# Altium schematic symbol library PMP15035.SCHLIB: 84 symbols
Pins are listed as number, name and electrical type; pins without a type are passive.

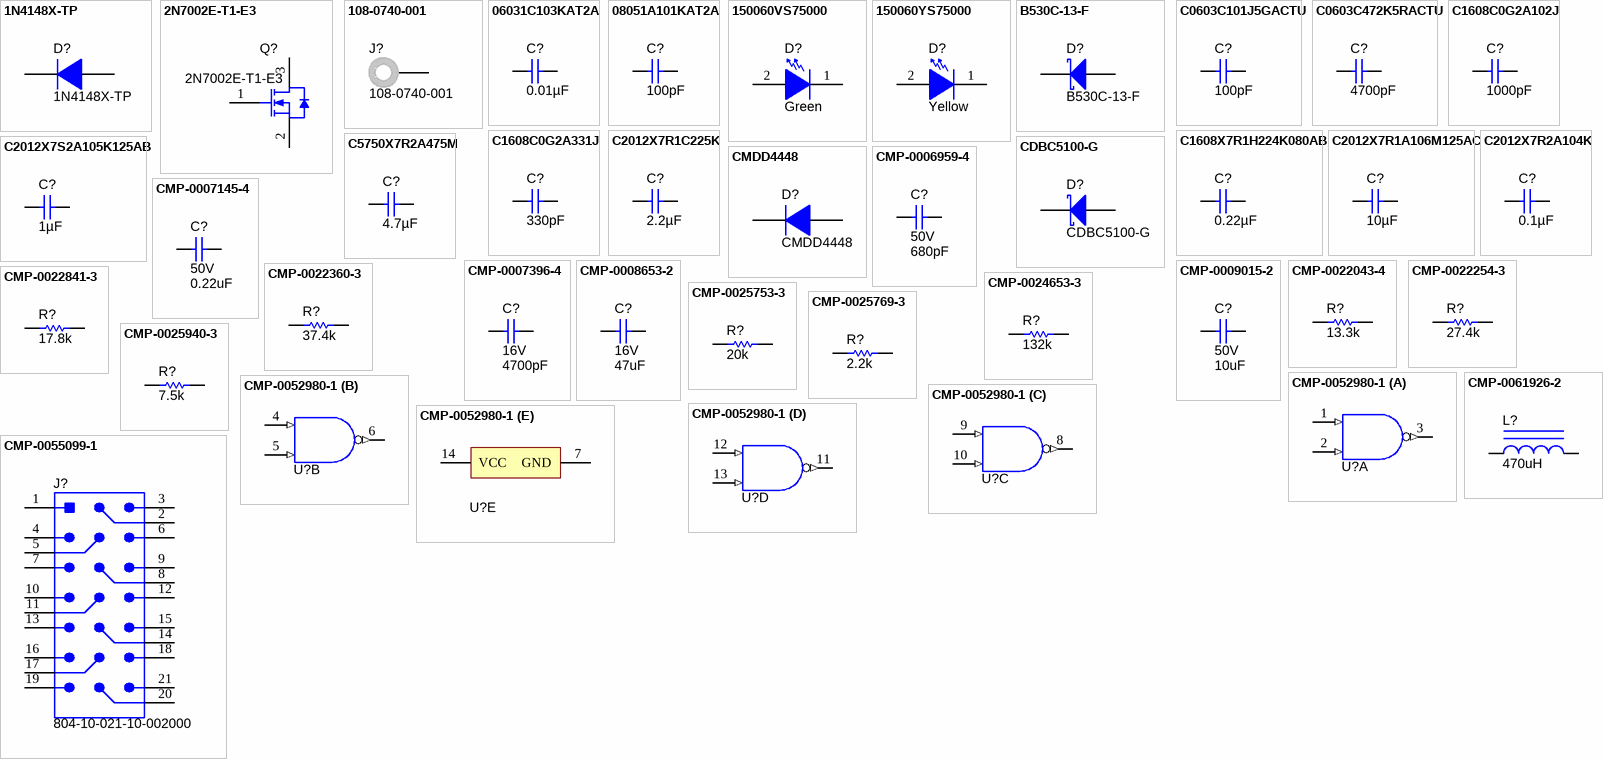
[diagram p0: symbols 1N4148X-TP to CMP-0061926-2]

## 1N4148X-TP
designator D?
Diode, Switching, 75 V, 0.3 A, SOD-523; Manufacturer: Micro Commercial Components; U/M: EA; Vf_V: 1.25; Value: 75V; Value1: 0.3A; Value2: 1.25V; Io_A: 0.3; Vr_V: 75; TJmax_C: 150; RJC_CperW: 625
signal-integrity model Diode
footprint SOD-523
pins: 1 K, 2 A

## 2N7002E-T1-E3
designator Q?
MOSFET, N-CH, 60 V, 0.24 A, SOT-23; Manufacturer: Vishay-Siliconix; Alternate Manufacturer: None; U/M: EA; ChType: N; Value: 60V; VdsMax_V: 60; Value1: 1.8 ohm; Rdson45_ohm: 1.8; Value2: 0.4 nC; QgTyp_nC: 0.4; Vgs_V: 20; IdsMax_A: 0.24
footprint SOT-23
footprint SOT-23M
footprint SOT-23L
simulation model 2N7002E
pins: 1 G, 2 S, 3 D

## 108-0740-001
designator J?
Standard Banana Jack, Uninsulated, 15A; Manufacturer: Emerson Network Power; SymbolCreator: a0412235; CompType: Connector; U/M: EA
footprint Johnson_108-0740-001
pins: 1

## 06031C103KAT2A
designator C?  ValueDisplayed: 0.01µF  (hidden comment: 06031C103KAT2A)
CAP, CERM, 0.01 µF, 100 V, +/- 10%, X7R, 0603; Manufacturer: AVX; Polarized: N; CompType: Capacitor; Value: 0.01uF; U/M: EA; Cap_F: 0.00000001; Tolerance_%: 10; ESR_ohm: 0.098; Value1: 0.098 ohm; VDC_V: 100; Value2: 100V; TaMin_C: -55; TaMax_C: 125; Cap_Case: 0603
signal-integrity model Cap
simulation model Cap
footprint 0603
footprint 0603M
footprint 0603L
footprint 0603_HV
footprint 0603S
pins: 1, 2

## 08051A101KAT2A
designator C?  ValueDisplayed: 100pF  (hidden comment: 08051A101KAT2A)
CAP, CERM, 100 pF, 100 V, +/- 10%, C0G/NP0, 0805; Manufacturer: AVX; Polarized: N; CompType: Capacitor; Value: 100pF; U/M: EA; Cap_F: 0.0000000001; Tolerance_%: 10; ESR_ohm: 0.356; Value1: 0.356 ohm; VDC_V: 100; Value2: 100V; TaMin_C: -55; TaMax_C: 125; Cap_Case: 0805
signal-integrity model Cap
simulation model Cap
footprint 0805_HV
footprint 0805
footprint 0805M
footprint 0805L
pins: 1, 2

## 150060VS75000
designator D?  value Green  (hidden comment: 150060VS75000)
LED, Green, SMD; Manufacturer: Wurth Elektronik; Type: AlInGaP; Vf_V: 2; Value2: 2V; Io_A: 0.02; Value1: W; U/M: EA
signal-integrity model Diode
footprint WL-SMCW_GREEN
pins: 1 K, 2 A

## 150060YS75000
designator D?  value Yellow  (hidden comment: 150060YS75000)
LED, Yellow, SMD; Manufacturer: Wurth Elektronik; Type: AlInGaP; Vf_V: 2; Value2: 2V; Io_A: 0.02; Value1: W; U/M: EA
signal-integrity model Diode
footprint WL-SMCW_YELLOW
pins: 1 K, 2 A

## B530C-13-F
designator D?
Diode, Schottky, 30 V, 5 A, SMC; Manufacturer: Diodes Inc.; U/M: EA; Vf_V: 0.55; Value: 30V; Value1: 5A; Value2: 0.55V; Io_A: 5; Vr_V: 30; TJmax_C: 125; RJC_CperW: 10
signal-integrity model Diode
simulation model DI_B530C
footprint SMC
pins: 1 K, 2 A

## C0603C101J5GACTU
designator C?  ValueDisplayed: 100pF  (hidden comment: C0603C101J5GACTU)
CAP, CERM, 100 pF, 50 V, +/- 5%, C0G/NP0, 0603; Manufacturer: Kemet; Polarized: N; CompType: Capacitor; Value: 100pF; U/M: EA; Cap_F: 0.0000000001; Tolerance_%: 5; Value1: Unknown; VDC_V: 50; Value2: 50V; TaMin_C: -55; TaMax_C: 125; Cap_Case: 0603; AEC Category: Q200
signal-integrity model Cap
simulation model Cap
footprint 0603
footprint 0603M
footprint 0603L
footprint 0603_HV
footprint 0603S
pins: 1, 2

## C0603C472K5RACTU
designator C?  ValueDisplayed: 4700pF  (hidden comment: C0603C472K5RACTU)
CAP, CERM, 4700 pF, 50 V, +/- 10%, X7R, 0603; Manufacturer: Kemet; Polarized: N; CompType: Capacitor; Value: 4700pF; U/M: EA; Cap_F: 0.0000000047; Tolerance_%: 10; Value1: Unknown; VDC_V: 50; Value2: 50V; TaMin_C: -55; TaMax_C: 125; Cap_Case: 0603; AEC Category: Q200
signal-integrity model Cap
simulation model Cap
footprint 0603
footprint 0603M
footprint 0603L
footprint 0603_HV
footprint 0603S
pins: 1, 2

## C1608C0G2A102J
designator C?  ValueDisplayed: 1000pF  (hidden comment: C1608C0G2A102J)
CAP, CERM, 1000 pF, 100 V, +/- 5%, C0G/NP0, 0603; Manufacturer: TDK; Polarized: N; CompType: Capacitor; Value: 1000pF; U/M: EA; Cap_F: 0.000000001; Tolerance_%: 5; ESR_ohm: 0.0589; Value1: 0.0589 ohm; VDC_V: 100; Value2: 100V; TaMin_C: -55; TaMax_C: 125; Cap_Case: 0603
signal-integrity model Cap
simulation model Cap
footprint 0603
footprint 0603M
footprint 0603L
footprint 0603_HV
footprint 0603S
pins: 1, 2

## C1608C0G2A331J
designator C?  ValueDisplayed: 330pF  (hidden comment: C1608C0G2A331J)
CAP, CERM, 330 pF, 100 V, +/- 5%, C0G/NP0, 0603; Manufacturer: TDK; Polarized: N; CompType: Capacitor; Value: 330pF; U/M: EA; Cap_F: 0.00000000033; Tolerance_%: 5; ESR_ohm: 0.1269; Value1: 0.1269 ohm; VDC_V: 100; Value2: 100V; TaMin_C: -55; TaMax_C: 125; Cap_Case: 0603
signal-integrity model Cap
simulation model Cap
footprint 0603
footprint 0603M
footprint 0603L
footprint 0603_HV
footprint 0603S
pins: 1, 2

## C1608X7R1H224K080AB
designator C?  ValueDisplayed: 0.22µF  (hidden comment: C1608X7R1H224K080AB)
CAP, CERM, 0.22 µF, 50 V, +/- 10%, X7R, 0603; Manufacturer: TDK; Polarized: N; CompType: Capacitor; Value: 0.22uF; U/M: EA; Cap_F: 0.00000022; Tolerance_%: 10; Value1: Unknown; VDC_V: 50; Value2: 50V; TaMin_C: -55; TaMax_C: 125; Cap_Case: 0603
signal-integrity model Cap
simulation model Cap
footprint 0603
footprint 0603M
footprint 0603L
footprint 0603_HV
footprint 0603S
pins: 1, 2

## C2012X7R1A106M125AC
designator C?  ValueDisplayed: 10µF  (hidden comment: C2012X7R1A106M125AC)
CAP, CERM, 10 µF, 10 V, +/- 20%, X7R, 0805; Manufacturer: TDK; Polarized: N; CompType: Capacitor; Value: 10uF; U/M: EA; Cap_F: 0.00001; Tolerance_%: 20; Value1: Unknown; VDC_V: 10; Value2: 10V; TaMin_C: -55; TaMax_C: 125; Cap_Case: 0805
signal-integrity model Cap
simulation model Cap
footprint 0805_145
footprint 0805_145M
footprint 0805_145L
footprint 0805_145HV
pins: 1, 2

## C2012X7R1C225K
designator C?  ValueDisplayed: 2.2µF  (hidden comment: C2012X7R1C225K)
CAP, CERM, 2.2 µF, 16 V, +/- 10%, X7R, 0805; Manufacturer: TDK; CompType: Capacitor; Value: 2.2uF; U/M: EA; Tolerance_%: 10; VDC_V: 16; Polarized: N; Cap_F: 0.0000022; ESR_ohm: 0.0049; Value1: 0.0049 ohm; Value2: 16V; TaMin_C: -55; TaMax_C: 125; Cap_Case: 0805
signal-integrity model Cap
simulation model Cap
footprint 0805_HV
footprint 0805
footprint 0805M
footprint 0805L
pins: 1, 2

## C2012X7R2A104K
designator C?  ValueDisplayed: 0.1µF  (hidden comment: C2012X7R2A104K)
CAP, CERM, 0.1 µF, 100 V, +/- 10%, X7R, 0805; Manufacturer: TDK; Polarized: N; CompType: Capacitor; Value: 0.1uF; U/M: EA; Cap_F: 0.0000001; Tolerance_%: 10; ESR_ohm: 0.0158; Value1: 0.0158 ohm; VDC_V: 100; Value2: 100V; TaMin_C: -55; TaMax_C: 125; Cap_Case: 0805
signal-integrity model Cap
simulation model Cap
footprint 0805_HV
footprint 0805
footprint 0805M
footprint 0805L
pins: 1, 2

## C2012X7S2A105K125AB
designator C?  ValueDisplayed: 1µF  (hidden comment: C2012X7S2A105K125AB)
CAP, CERM, 1 µF, 100 V, +/- 10%, X7S, 0805; Manufacturer: TDK; Polarized: N; CompType: Capacitor; Value: 1uF; U/M: EA; Cap_F: 0.000001; Tolerance_%: 10; Value1: Unknown; VDC_V: 100; Value2: 100V; TaMin_C: -55; TaMax_C: 125; Cap_Case: 0805; AEC Category: Q200
signal-integrity model Cap
simulation model Cap
footprint 0805_HV
footprint 0805_HV1
footprint 0805
footprint 0805M
footprint 0805L
pins: 1, 2

## C5750X7R2A475M
designator C?  ValueDisplayed: 4.7µF  (hidden comment: C5750X7R2A475M)
CAP, CERM, 4.7 µF, 100 V, +/- 20%, X7R, 2220; Manufacturer: TDK; Polarized: N; CompType: Capacitor; Value: 4.7uF; U/M: EA; Cap_F: 0.0000047; Tolerance_%: 20; ESR_ohm: 0.0015; Value1: 0.0015 ohm; VDC_V: 100; Value2: 100V; IRMS_A: 5.5; TaMin_C: -55; TaMax_C: 125; Cap_Case: 2220
signal-integrity model Cap
simulation model Cap
footprint 2220
footprint 2220_M
footprint 2220_L
pins: 1, 2

## CDBC5100-G
designator D?
Diode, Schottky, 100 V, 5 A, SMC; Manufacturer: Comchip Technology; U/M: EA; Vf_V: 0.85; Value: 100V; Value1: 5A; Value2: 0.85V; Io_A: 5; Vr_V: 100; TJmax_C: 125
signal-integrity model Diode
footprint SMC
pins: 1 K, 2 A

## CMDD4448
designator D?
Diode, Ultrafast, 75 V, 0.25 A, SOD-323; Manufacturer: Central Semiconductor; U/M: EA; Vf_V: 1.2; Value: 75V; Value1: 0.25A; Value2: 1.2V; Io_A: 0.25; Vr_V: 75; TJmax_C: 175
signal-integrity model Diode
simulation model CMDD4448
footprint sod-323
pins: 1 K, 2 A

## CMP-0006959-4
designator C?, comment VDC_V: 50V  ValueDisplayed: 680pF  (hidden comment: C0603C681J5GACTU)
CAP, CERM, 680 pF, 50 V, +/- 5%, C0G/NP0, 0603; Manufacturer: Kemet; TaMin_C: -55°C; Polarized: N; SizeAreaWB_mm2: 4.68; Value1: Unknown; U/M: EA; Value: 680pF; TaMax_C: 125°C; SizeZ_mm: 1; SizeX_mm: 1.6; SizeY_mm: 0.8; Cap_Case: 0603; SizeArea_mm2: 1.28; CompType: Capacitor; AEC Category: Q200
footprint 0603 (0603 from SM-752 data)
footprint 0603_HV (Ernesto recommended land pattern.  26 mil between pads.)
footprint 0603L (0603 from SM-752 data)
footprint 0603S
footprint 0603M (0603 from SM-752 data)
pins: 1, 2

## CMP-0007145-4
designator C?, comment VDC_V: 50V  ValueDisplayed: 0.22uF  (hidden comment: GCM188R71H224KA64D)
CAP, CERM, 0.22 uF, 50 V, +/- 10%, X7R, AEC-Q200 Grade 1, 0603; Manufacturer: MuRata; TaMin_C: -55°C; Polarized: N; SizeAreaWB_mm2: 4.68; Value1: Unknown; U/M: EA; Value: 0.22uF; TaMax_C: 125°C; SizeZ_mm: 1; SizeX_mm: 1.6; SizeY_mm: 0.8; Cap_Case: 0603; SizeArea_mm2: 1.28; CompType: Capacitor; AEC Qualified: Y; Cap_F: 220nF; AEC Category: Q200
footprint 0603 (0603 from SM-752 data)
footprint 0603_HV (Ernesto recommended land pattern.  26 mil between pads.)
footprint 0603L (0603 from SM-752 data)
footprint 0603S
footprint 0603M (0603 from SM-752 data)
pins: 1, 2

## CMP-0007396-4
designator C?, comment VDC_V: 16V  ValueDisplayed: 4700pF  (hidden comment: GRM188R71C472KA01D)
CAP, CERM, 4700 pF, 16 V, +/- 10%, X7R, 0603; Manufacturer: MuRata; TaMin_C: -55°C; Polarized: N; SizeAreaWB_mm2: 4.68; Value1: Unknown; U/M: EA; Value: 4700pF; TaMax_C: 125°C; SizeZ_mm: 1; SizeX_mm: 1.6; SizeY_mm: 0.8; Cap_Case: 0603; SizeArea_mm2: 1.28; Cap_F: 4.7nF; AEC Category: Q200; CompType: Capacitor
footprint 0603 (0603 from SM-752 data)
footprint 0603_HV (Ernesto recommended land pattern.  26 mil between pads.)
footprint 0603L (0603 from SM-752 data)
footprint 0603S
footprint 0603M (0603 from SM-752 data)
pins: 1, 2

## CMP-0008653-2
designator C?, comment VDC_V: 16V  ValueDisplayed: 47uF  (hidden comment: C3216X5R1C476M160AB)
CAP, CERM, 47 uF, 16 V, +/- 15%, X5R, 1206; Manufacturer: TDK; TaMin_C: -55°C; Polarized: N; SizeAreaWB_mm2: 10.92; Value1: Unknown; U/M: EA; Value: 47uF; TaMax_C: 85°C; SizeZ_mm: 1.35; SizeX_mm: 3.2; SizeY_mm: 1.6; Cap_Case: 1206; SizeArea_mm2: 5.12; CompType: Capacitor; Cap_F: 47µF; AEC Category: Q200
footprint 1206 (1206 from SM-752 data)
footprint 1206L (1206 from SM-752 data)
footprint 1206M (1206 from SM-752 data)
pins: 1, 2

## CMP-0009015-2
designator C?, comment VDC_V: 50V  ValueDisplayed: 10uF  (hidden comment: GRT31CR61H106KE01L)
CAP, CERM, 10 uF, 50 V, +/- 10%, X5R, AEC-Q200 Grade 1, 1206; Manufacturer: MuRata; TaMin_C: -55°C; Polarized: N; SizeAreaWB_mm2: 10.92; Value1: Unknown; U/M: EA; Value: 10uF; TaMax_C: 85°C; SizeZ_mm: 1.8; SizeX_mm: 3.2; SizeY_mm: 1.6; Cap_Case: 1206; SizeArea_mm2: 5.12; CompType: Capacitor; AEC Qualified: Y; Cap_F: 10µF; AEC Grade: 1; AEC Category: Q200
footprint 1206_180
footprint 1206_180L (1206_180)
footprint 1206_180M (1206_180)
pins: 1, 2

## CMP-0022043-4
designator R?, comment ValueDisplayed: 13.3k  (hidden comment: CRCW060313K3FKEA)
RES, 13.3 k, 1%, 0.1 W, AEC-Q200 Grade 0, 0603; Manufacturer: Vishay-Dale; Power_W: 100mW; TempCo: 100 ppm/C; Value_Code: 13k3; Value: 13.3k; EIA_Code: E96; SizeX_mm: 1.6; SizeY_mm: 0.8; SizeZ_mm: 1; Value2: 0.1W; SizeArea_mm2: 1.28; CompType: Resistor; AEC Qualified: Y; VDC_V: 75V; AEC Category: Q200; AEC Grade: 0
footprint 0603 (0603 from SM-752 data)
footprint 0603_HV (Ernesto recommended land pattern.  26 mil between pads.)
footprint 0603L (0603 from SM-752 data)
footprint 0603S
footprint 0603M (0603 from SM-752 data)
pins: 1, 2

## CMP-0022254-3
designator R?, comment ValueDisplayed: 27.4k  (hidden comment: CRCW060327K4FKEA)
RES, 27.4 k, 1%, 0.1 W, 0603; Manufacturer: Vishay-Dale; Power_W: 100mW; TempCo: 100 ppm/C; Value_Code: 27k4; U/M: EA; Value: 27.4k; EIA_Code: E96; SizeX_mm: 1.6; SizeY_mm: 0.8; SizeZ_mm: 1; Value2: 0.1W; SizeArea_mm2: 1.28; CompType: Resistor; VDC_V: 75V; AEC Category: Q200
footprint 0603 (0603 from SM-752 data)
footprint 0603_HV (Ernesto recommended land pattern.  26 mil between pads.)
footprint 0603L (0603 from SM-752 data)
footprint 0603S
footprint 0603M (0603 from SM-752 data)
pins: 1, 2

## CMP-0022360-3
designator R?, comment ValueDisplayed: 37.4k  (hidden comment: CRCW060337K4FKEA)
RES, 37.4 k, 1%, 0.1 W, 0603; Manufacturer: Vishay-Dale; Power_W: 100mW; TempCo: 100 ppm/C; Value_Code: 37k4; U/M: EA; Value: 37.4k; EIA_Code: E96; SizeX_mm: 1.6; SizeY_mm: 0.8; SizeZ_mm: 1; Value2: 0.1W; SizeArea_mm2: 1.28; CompType: Resistor; VDC_V: 75V; AEC Category: Q200
footprint 0603 (0603 from SM-752 data)
footprint 0603_HV (Ernesto recommended land pattern.  26 mil between pads.)
footprint 0603L (0603 from SM-752 data)
footprint 0603S
footprint 0603M (0603 from SM-752 data)
pins: 1, 2

## CMP-0022841-3
designator R?, comment ValueDisplayed: 17.8k  (hidden comment: RC0603FR-0717K8L)
RES, 17.8 k, 1%, 0.1 W, 0603; Manufacturer: Yageo America; Power_W: 100mW; TempCo: 200 ppm/C; Value_Code: 17k8; U/M: EA; Value: 17.8k; EIA_Code: E96; SizeX_mm: 1.6; SizeY_mm: 0.8; SizeZ_mm: 1; Value2: 0.1W; SizeArea_mm2: 1.28; CompType: Resistor; VDC_V: 150V; AEC Category: Q200
footprint 0603 (0603 from SM-752 data)
footprint 0603_HV (Ernesto recommended land pattern.  26 mil between pads.)
footprint 0603L (0603 from SM-752 data)
footprint 0603S
footprint 0603M (0603 from SM-752 data)
pins: 1, 2

## CMP-0024653-3
designator R?, comment ValueDisplayed: 132k  (hidden comment: RT0603DRE07132KL)
RES, 132 k, 0.5%, 0.1 W, 0603; Manufacturer: Yageo America; Power_W: 100mW; TempCo: 50 ppm/C; U/M: EA; Value: 132k; EIA_Code: E192; SizeX_mm: 1.6; SizeY_mm: 0.8; SizeZ_mm: 1; Value2: 0.1W; SizeArea_mm2: 1.28; CompType: Resistor; VDC_V: 75V; AEC Category: Q200
footprint 0603 (0603 from SM-752 data)
footprint 0603_HV (Ernesto recommended land pattern.  26 mil between pads.)
footprint 0603L (0603 from SM-752 data)
footprint 0603S
footprint 0603M (0603 from SM-752 data)
pins: 1, 2

## CMP-0025753-3
designator R?, comment ValueDisplayed: 20k  (hidden comment: CRCW060320K0JNEA)
RES, 20 k, 5%, 0.1 W, 0603; Manufacturer: Vishay-Dale; Power_W: 100mW; TempCo: 200 ppm/C; Value_Code: 20k0; U/M: EA; Value: 20k; EIA_Code: E24; SizeX_mm: 1.6; SizeY_mm: 0.8; SizeZ_mm: 1; Value2: 0.1W; SizeArea_mm2: 1.28; CompType: Resistor; VDC_V: 75V; AEC Category: Q200
footprint 0603 (0603 from SM-752 data)
footprint 0603_HV (Ernesto recommended land pattern.  26 mil between pads.)
footprint 0603L (0603 from SM-752 data)
footprint 0603S
footprint 0603M (0603 from SM-752 data)
pins: 1, 2

## CMP-0025769-3
designator R?, comment ValueDisplayed: 2.2k  (hidden comment: CRCW06032K20JNEA)
RES, 2.2 k, 5%, 0.1 W, 0603; Manufacturer: Vishay-Dale; Power_W: 100mW; TempCo: 200 ppm/C; Value_Code: 2k20; U/M: EA; Value: 2.2k; EIA_Code: E24; SizeX_mm: 1.6; SizeY_mm: 0.8; SizeZ_mm: 1; Value2: 0.1W; SizeArea_mm2: 1.28; CompType: Resistor; VDC_V: 75V; AEC Category: Q200
footprint 0603 (0603 from SM-752 data)
footprint 0603_HV (Ernesto recommended land pattern.  26 mil between pads.)
footprint 0603L (0603 from SM-752 data)
footprint 0603S
footprint 0603M (0603 from SM-752 data)
pins: 1, 2

## CMP-0025940-3
designator R?, comment ValueDisplayed: 7.5k  (hidden comment: RC0603JR-077K5L)
RES, 7.5 k, 5%, 0.1 W, 0603; Manufacturer: Yageo America; Power_W: 100mW; TempCo: 100 ppm/C; Value_Code: 7k50; U/M: EA; Value: 7.5k; EIA_Code: E24; SizeX_mm: 1.6; SizeY_mm: 0.8; SizeZ_mm: 1; Value2: 0.1W; SizeArea_mm2: 1.28; CompType: Resistor; VDC_V: 50V; AEC Category: Q200
footprint 0603 (0603 from SM-752 data)
footprint 0603_HV (Ernesto recommended land pattern.  26 mil between pads.)
footprint 0603L (0603 from SM-752 data)
footprint 0603S
footprint 0603M (0603 from SM-752 data)
pins: 1, 2

## CMP-0052980-1
designator U?, comment SN74ACT00TDRQ1  (value not drawn)
Automotive Catalog Quadruple 2-Input Positive-NAND Gates, D0014A, LARGE T&R; Generic Part Number: SN74ACT00-Q1; Manufacturer: Texas Instruments; Voltage(Nom)(V): 5; Bits(#): 4; VCC(Min)(V): 4.5; Technology Family: ACT; tpd @ Nom Voltage(Max)(ns): 9.5; Output Type: CMOS; Input Type: TTL; Output Drive (IOL/IOH)(Max)(mA): 24/-24; ICC @ Nom Voltage(Max)(mA): 0.02; VCC(Max)(V): 5.5; Schmitt Trigger: No; F @ Nom Voltage(Max)(Mhz): 90
footprint D0014A_N (SOIC, 14-Leads, Body 8.7x3.9mm, Pitch 1.27mm, IPC Medium Density)
footprint D0014A_M (SOIC, 14-Leads, Body 8.7x3.9mm, Pitch 1.27mm, IPC Low Density)
footprint D0014A_L (SOIC, 14-Leads, Body 8.7x3.9mm, Pitch 1.27mm, IPC High Density)
part A pins: 1 1A (in) "Gate 1 input", 2 1B (in) "Gate 1 input", 3 1Y (out) "Gate 1 output"
part B pins: 4 2A (in) "Gate 2 input", 5 2B (in) "Gate 2 input", 6 2Y (out) "Gate 2 output"
part C pins: 8 3Y (out) "Gate 3 output", 9 3A (in) "Gate 3 input", 10 3B (in) "Gate 3 input"
part D pins: 11 4Y (out) "Gate 4 output", 12 4A (in) "Gate 4 input", 13 4B (in) "Gate 4 input"
part E pins: 7 GND (power) "Ground Pin", 14 VCC (power) "Power Pin"

## CMP-0055099-1
designator J?, comment 804-10-021-10-002000
Header, 2.54 mm, 7x3, Gold, Vertical, TH; Manufacturer: Mill-Max; CNHeader: TRUE; Shrouded: N; Gender: Male; Row_Count: 3; RowSpacing_mm: 2.54; CT: FALSE
footprint Mill-Max_804-10-021-10-002000 (Header, 2.54 mm, 7x3, TH)
pins: 1, 2, 3, 4, 5, 6, 7, 8, 9, 10, 11, 12, 13, 14, 15, 16, 17, 18, 19, 20, 21

## CMP-0061926-2
designator L?, comment ValueDisplayed: 470uH  (hidden comment: MSS1278-474KLB)
Inductor, Shielded Drum Core, Ferrite, 470 uH, 0.9 A, 0.71 ohm, SMD; Manufacturer: Coilcraft; Isat: 1.64A @ 30% inductance drop; Irms: 0.9A @ 40C rise; Green_Lifecycle: Not Set; SizeAreaWB_mm2: 204.49; DCR_ohm: 7.1d; Green_REACh: Incomplete; Value: 470uH; Imax_A: 9dA; SizeZ_mm: 8.05; SizeX_mm: 12.3; Value2: 0.9A; SizeArea_mm2: 151.29; Ind_H: 470µH; AEC Category: Q200
footprint MSS1278 (Coilcraft recommended land pattern.  Document 598-2 rev 04/04/13)
pins: 1, 2

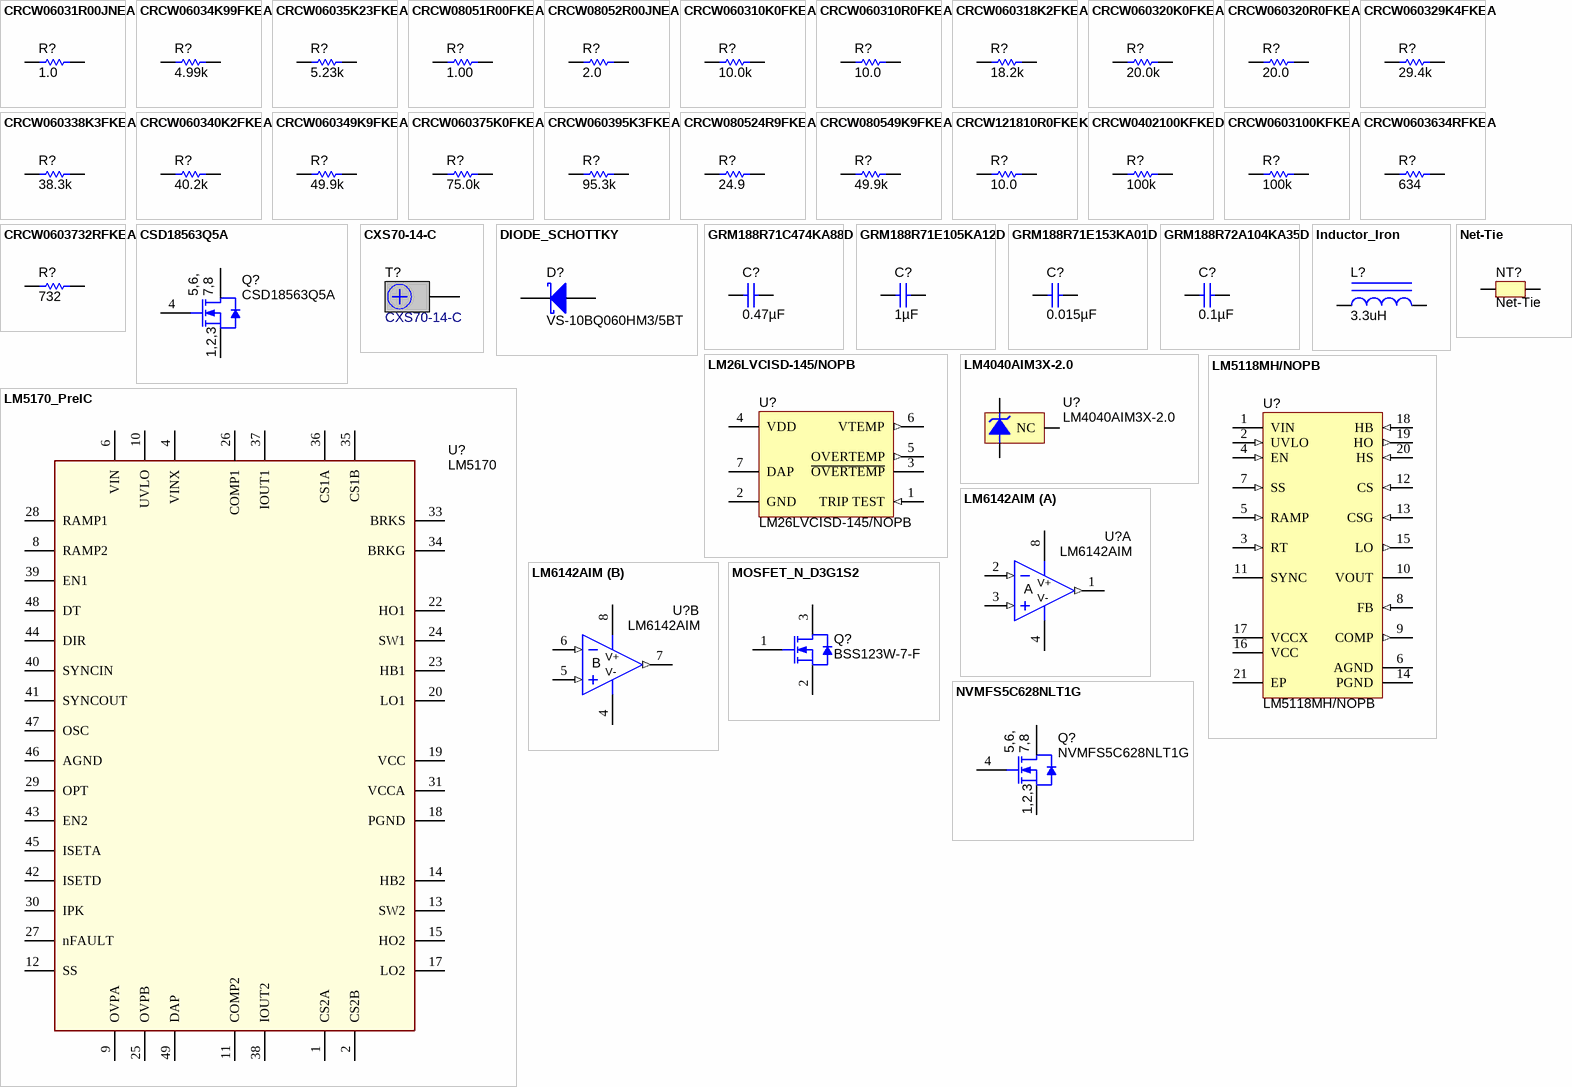
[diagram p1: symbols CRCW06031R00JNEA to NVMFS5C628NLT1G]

## CRCW06031R00JNEA
designator R?  ValueDisplayed: 1.0  (hidden comment: CRCW06031R00JNEA)
RES, 1.0, 5%, 0.1 W, 0603; Manufacturer: Vishay-Dale; CompType: Resistor; Value: 1.0; Res_ohm: 1; Value_Code: 1R00; Tolerance_%: 5; Power_W: 0.1; Value2: 0.1W; VDC_V: 75; TempCo: 200 ppm/C; EIA_Code: E24; U/M: EA; AEC Category: Q200
signal-integrity model Resistor
simulation model Resistor
footprint 0603
footprint 0603M
footprint 0603L
footprint 0603_HV
footprint 0603S
pins: 1, 2

## CRCW06034K99FKEA
designator R?  ValueDisplayed: 4.99k  (hidden comment: CRCW06034K99FKEA)
RES, 4.99 k, 1%, 0.1 W, 0603; Manufacturer: Vishay-Dale; CompType: Resistor; Value: 4.99k; Res_ohm: 4990; Value_Code: 4k99; Tolerance_%: 1; Power_W: 0.1; Value2: 0.1W; VDC_V: 75; TempCo: 100 ppm/C; EIA_Code: E96; U/M: EA
signal-integrity model Resistor
simulation model Resistor
footprint 0603
footprint 0603M
footprint 0603L
footprint 0603_HV
footprint 0603S
pins: 1, 2

## CRCW06035K23FKEA
designator R?  ValueDisplayed: 5.23k  (hidden comment: CRCW06035K23FKEA)
RES, 5.23 k, 1%, 0.1 W, 0603; Manufacturer: Vishay-Dale; CompType: Resistor; Value: 5.23k; Res_ohm: 5230; Value_Code: 5k23; Tolerance_%: 1; Power_W: 0.1; Value2: 0.1W; VDC_V: 75; TempCo: 100 ppm/C; EIA_Code: E96; U/M: EA
signal-integrity model Resistor
simulation model Resistor
footprint 0603
footprint 0603M
footprint 0603L
footprint 0603_HV
footprint 0603S
pins: 1, 2

## CRCW08051R00FKEA
designator R?  ValueDisplayed: 1.00  (hidden comment: CRCW08051R00FKEA)
RES, 1.00, 1%, 0.125 W, 0805; Manufacturer: Vishay-Dale; CompType: Resistor; Value: 1.00; Res_ohm: 1; Value_Code: 1R00; Power_W: 0.125; Value2: 0.125W; VDC_V: 150; TempCo: 100 ppm/C; EIA_Code: E96; U/M: EA
signal-integrity model Resistor
simulation model Resistor
footprint 0805_HV
footprint 0805
footprint 0805M
footprint 0805L
pins: 1, 2

## CRCW08052R00JNEA
designator R?  ValueDisplayed: 2.0  (hidden comment: CRCW08052R00JNEA)
RES, 2.0, 5%, 0.125 W, 0805; Manufacturer: Vishay-Dale; CompType: Resistor; Value: 2.0; Res_ohm: 2; Value_Code: 2R00; Tolerance_%: 5; Power_W: 0.125; Value2: 0.125W; VDC_V: 150; TempCo: 200 ppm/C; EIA_Code: E24; U/M: EA; AEC Category: Q200
signal-integrity model Resistor
simulation model Resistor
footprint 0805_HV
footprint 0805_HV1
footprint 0805
footprint 0805M
pins: 1, 2

## CRCW060310K0FKEA
designator R?  ValueDisplayed: 10.0k  (hidden comment: CRCW060310K0FKEA)
RES, 10.0 k, 1%, 0.1 W, 0603; Manufacturer: Vishay-Dale; CompType: Resistor; Value: 10.0k; Res_ohm: 10000; Value_Code: 10k0; Tolerance_%: 1; Power_W: 0.1; Value2: 0.1W; VDC_V: 75; TempCo: 100 ppm/C; EIA_Code: E96; U/M: EA
signal-integrity model Resistor
simulation model Resistor
footprint 0603
footprint 0603M
footprint 0603L
footprint 0603_HV
footprint 0603S
pins: 1, 2

## CRCW060310R0FKEA
designator R?  ValueDisplayed: 10.0  (hidden comment: CRCW060310R0FKEA)
RES, 10.0, 1%, 0.1 W, 0603; Manufacturer: Vishay-Dale; CompType: Resistor; Value: 10.0; Res_ohm: 10; Value_Code: 10R0; Tolerance_%: 1; Power_W: 0.1; Value2: 0.1W; VDC_V: 75; TempCo: 100 ppm/C; EIA_Code: E96; U/M: EA
signal-integrity model Resistor
simulation model Resistor
footprint 0603
footprint 0603M
footprint 0603L
footprint 0603_HV
footprint 0603S
pins: 1, 2

## CRCW060318K2FKEA
designator R?  ValueDisplayed: 18.2k  (hidden comment: CRCW060318K2FKEA)
RES, 18.2 k, 1%, 0.1 W, 0603; Manufacturer: Vishay-Dale; CompType: Resistor; Value: 18.2k; Res_ohm: 18200; Value_Code: 18k2; Tolerance_%: 1; Power_W: 0.1; Value2: 0.1W; VDC_V: 75; TempCo: 100 ppm/C; EIA_Code: E96; U/M: EA
signal-integrity model Resistor
simulation model Resistor
footprint 0603
footprint 0603M
footprint 0603L
footprint 0603_HV
footprint 0603S
pins: 1, 2

## CRCW060320K0FKEA
designator R?  ValueDisplayed: 20.0k  (hidden comment: CRCW060320K0FKEA)
RES, 20.0 k, 1%, 0.1 W, 0603; Manufacturer: Vishay-Dale; CompType: Resistor; Value: 20.0k; Res_ohm: 20000; Value_Code: 20k0; Tolerance_%: 1; Power_W: 0.1; Value2: 0.1W; VDC_V: 75; TempCo: 100 ppm/C; EIA_Code: E96; U/M: EA
signal-integrity model Resistor
simulation model Resistor
footprint 0603
footprint 0603M
footprint 0603L
footprint 0603_HV
footprint 0603S
pins: 1, 2

## CRCW060320R0FKEA
designator R?  ValueDisplayed: 20.0  (hidden comment: CRCW060320R0FKEA)
RES, 20.0, 1%, 0.1 W, 0603; Manufacturer: Vishay-Dale; CompType: Resistor; Value: 20.0; Res_ohm: 20; Value_Code: 20R0; Tolerance_%: 1; Power_W: 0.1; Value2: 0.1W; VDC_V: 75; TempCo: 100 ppm/C; EIA_Code: E96; U/M: EA
signal-integrity model Resistor
simulation model Resistor
footprint 0603
footprint 0603M
footprint 0603L
footprint 0603_HV
footprint 0603S
pins: 1, 2

## CRCW060329K4FKEA
designator R?  ValueDisplayed: 29.4k  (hidden comment: CRCW060329K4FKEA)
RES, 29.4 k, 1%, 0.1 W, 0603; Manufacturer: Vishay-Dale; CompType: Resistor; Value: 29.4k; Res_ohm: 29400; Value_Code: 29k4; Tolerance_%: 1; Power_W: 0.1; Value2: 0.1W; VDC_V: 75; TempCo: 100 ppm/C; EIA_Code: E96; U/M: EA
signal-integrity model Resistor
simulation model Resistor
footprint 0603
footprint 0603M
footprint 0603L
footprint 0603_HV
footprint 0603S
pins: 1, 2

## CRCW060338K3FKEA
designator R?  ValueDisplayed: 38.3k  (hidden comment: CRCW060338K3FKEA)
RES, 38.3 k, 1%, 0.1 W, 0603; Manufacturer: Vishay-Dale; CompType: Resistor; Value: 38.3k; Res_ohm: 38300; Value_Code: 38k3; Tolerance_%: 1; Power_W: 0.1; Value2: 0.1W; VDC_V: 75; TempCo: 100 ppm/C; EIA_Code: E96; U/M: EA
signal-integrity model Resistor
simulation model Resistor
footprint 0603
footprint 0603M
footprint 0603L
footprint 0603_HV
footprint 0603S
pins: 1, 2

## CRCW060340K2FKEA
designator R?  ValueDisplayed: 40.2k  (hidden comment: CRCW060340K2FKEA)
RES, 40.2 k, 1%, 0.1 W, 0603; Manufacturer: Vishay-Dale; CompType: Resistor; Value: 40.2k; Res_ohm: 40200; Value_Code: 40k2; Tolerance_%: 1; Power_W: 0.1; Value2: 0.1W; VDC_V: 75; TempCo: 100 ppm/C; EIA_Code: E96; U/M: EA; AEC Category: Q200
signal-integrity model Resistor
simulation model Resistor
footprint 0603
footprint 0603M
footprint 0603L
footprint 0603_HV
footprint 0603S
pins: 1, 2

## CRCW060349K9FKEA
designator R?  ValueDisplayed: 49.9k  (hidden comment: CRCW060349K9FKEA)
RES, 49.9 k, 1%, 0.1 W, 0603; Manufacturer: Vishay-Dale; CompType: Resistor; Value: 49.9k; Res_ohm: 49900; Value_Code: 49k9; Tolerance_%: 1; Power_W: 0.1; Value2: 0.1W; VDC_V: 75; TempCo: 100 ppm/C; EIA_Code: E96; U/M: EA
signal-integrity model Resistor
simulation model Resistor
footprint 0603
footprint 0603M
footprint 0603L
footprint 0603_HV
footprint 0603S
pins: 1, 2

## CRCW060375K0FKEA
designator R?  ValueDisplayed: 75.0k  (hidden comment: CRCW060375K0FKEA)
RES, 75.0 k, 1%, 0.1 W, 0603; Manufacturer: Vishay-Dale; CompType: Resistor; Value: 75.0k; Res_ohm: 75000; Value_Code: 75k0; Tolerance_%: 1; Power_W: 0.1; Value2: 0.1W; VDC_V: 75; TempCo: 100 ppm/C; EIA_Code: E96; U/M: EA
signal-integrity model Resistor
simulation model Resistor
footprint 0603
footprint 0603M
footprint 0603L
footprint 0603_HV
footprint 0603S
pins: 1, 2

## CRCW060395K3FKEA
designator R?  ValueDisplayed: 95.3k  (hidden comment: CRCW060395K3FKEA)
RES, 95.3 k, 1%, 0.1 W, 0603; Manufacturer: Vishay-Dale; CompType: Resistor; Value: 95.3k; Res_ohm: 95300; Value_Code: 95k3; Tolerance_%: 1; Power_W: 0.1; Value2: 0.1W; VDC_V: 75; TempCo: 100 ppm/C; EIA_Code: E96; U/M: EA
signal-integrity model Resistor
simulation model Resistor
footprint 0603
footprint 0603M
footprint 0603L
footprint 0603_HV
footprint 0603S
pins: 1, 2

## CRCW080524R9FKEA
designator R?  ValueDisplayed: 24.9  (hidden comment: CRCW080524R9FKEA)
RES, 24.9, 1%, 0.125 W, 0805; Manufacturer: Vishay-Dale; CompType: Resistor; Value: 24.9; Value_Code: 24R9; Tolerance_%: 1; Power_W: 0.125; Value2: 0.125W; VDC_V: 150; TempCo: 100 ppm/C; EIA_Code: E96; U/M: EA
signal-integrity model Resistor
simulation model Resistor
footprint 0805_HV
footprint 0805
footprint 0805M
footprint 0805L (0805 from SM-752 data)
pins: 1, 2

## CRCW080549K9FKEA
designator R?  ValueDisplayed: 49.9k  (hidden comment: CRCW080549K9FKEA)
RES, 49.9 k, 1%, 0.125 W, 0805; Manufacturer: Vishay-Dale; CompType: Resistor; Value: 49.9k; Res_ohm: 49900; Value_Code: 49k9; Tolerance_%: 1; Power_W: 0.125; Value2: 0.125W; VDC_V: 150; TempCo: 100 ppm/C; EIA_Code: E96; U/M: EA
signal-integrity model Resistor
simulation model Resistor
footprint 0805_HV
footprint 0805
footprint 0805M
footprint 0805L
pins: 1, 2

## CRCW121810R0FKEK
designator R?  ValueDisplayed: 10.0  (hidden comment: CRCW121810R0FKEK)
RES, 10.0, 1%, 1 W, 1218; Manufacturer: Vishay-Dale; CompType: Resistor; Value: 10.0; Res_ohm: 10; Value_Code: 10R0; Tolerance_%: 1; Value2: 1W; VDC_V: 200; TempCo: 100 ppm/C; EIA_Code: E96; U/M: EA
signal-integrity model Resistor
simulation model Resistor
footprint 1218
pins: 1, 2

## CRCW0402100KFKED
designator R?  ValueDisplayed: 100k  (hidden comment: CRCW0402100KFKED)
RES, 100 k, 1%, 0.063 W, 0402; Manufacturer: Vishay-Dale; CompType: Resistor; Value: 100k; Res_ohm: 100000; Tolerance_%: 1; Power_W: 0.063; Value2: 0.063W; VDC_V: 50; TempCo: 100 ppm/C; EIA_Code: E96; U/M: EA
signal-integrity model Resistor
simulation model Resistor
footprint 0402
footprint 0402M
footprint 0402L
footprint 0402S
pins: 1, 2

## CRCW0603100KFKEA
designator R?  ValueDisplayed: 100k  (hidden comment: CRCW0603100KFKEA)
RES, 100 k, 1%, 0.1 W, 0603; Manufacturer: Vishay-Dale; CompType: Resistor; Value: 100k; Res_ohm: 100000; Tolerance_%: 1; Power_W: 0.1; Value2: 0.1W; VDC_V: 75; TempCo: 100 ppm/C; EIA_Code: E96; U/M: EA
signal-integrity model Resistor
simulation model Resistor
footprint 0603
footprint 0603M
footprint 0603L
footprint 0603_HV
footprint 0603S
pins: 1, 2

## CRCW0603634RFKEA
designator R?  ValueDisplayed: 634  (hidden comment: CRCW0603634RFKEA)
RES, 634, 1%, 0.1 W, 0603; Manufacturer: Vishay-Dale; CompType: Resistor; Value: 634; Value_Code: 634R; Tolerance_%: 1; Power_W: 0.1; Value2: 0.1W; VDC_V: 75; TempCo: 100 ppm/C; EIA_Code: E96; U/M: EA
signal-integrity model Resistor
simulation model Resistor
footprint 0603
footprint 0603M
footprint 0603L
footprint 0603_HV
footprint 0603S
pins: 1, 2

## CRCW0603732RFKEA
designator R?  ValueDisplayed: 732  (hidden comment: CRCW0603732RFKEA)
RES, 732, 1%, 0.1 W, 0603; Manufacturer: Vishay-Dale; CompType: Resistor; Value: 732; Value_Code: 732R; Tolerance_%: 1; Power_W: 0.1; Value2: 0.1W; VDC_V: 75; TempCo: 100 ppm/C; EIA_Code: E96; U/M: EA
signal-integrity model Resistor
simulation model Resistor
footprint 0603
footprint 0603M
footprint 0603L
footprint 0603_HV
footprint 0603S
pins: 1, 2

## CSD18563Q5A
designator Q?
MOSFET, N-CH, 60 V, 15 A, SON 5x6mm; Manufacturer: Texas Instruments; Alternate Manufacturer: None; U/M: EA; ChType: N; Value: 60V; VdsMax_V: 60; Value1: 0.0086 ohm; Rdson45_ohm: 0.0086; Value2: 15 nC; QgTyp_nC: 15; Vgs_V: 20
footprint TRANS_NexFET_Q5A
pins: 1 S, 2 S, 3 S, 4 G, 5 D, 6 D, 7 D, 8 D, 9 D

## CXS70-14-C
designator T?
Terminal 70A Lug; Manufacturer: Panduit; SymbolCreator: crossc; CompType: Screw Terminal; U/M: EA
footprint Panduit_CXS70-14-C
pins: 1

## DIODE_SCHOTTKY
designator D?, comment VS-10BQ060HM3/5BT
Diode, Schottky, 60 V, 1 A, AEC-Q101, SMB; Manufacturer: Vishay-Semiconductor; Io_A: 1A; Green_Lifecycle: Not Set; SizeAreaWB_mm2: 44.156; Vr_V: 60V; Green_REACh: Incomplete; TJmax_C: 150°C; U/M: EA; Value: 60V; SizeZ_mm: 2.6; SizeX_mm: 5.6; SizeY_mm: 3.81; Vf_V: 4.9dV; Value2: 0.49V; SizeArea_mm2: 21.336; AEC Qualified: Y; AEC Category: Q101
footprint SMB (Molded Diode, 2-Leads, Body 5.4x3.6mm, IPC Medium Density, based on OnSemi component dimensions)
pins: 1 K, 2 A

## GRM188R71C474KA88D
designator C?  ValueDisplayed: 0.47µF  (hidden comment: GRM188R71C474KA88D)
CAP, CERM, 0.47 µF, 16 V, +/- 10%, X7R, 0603; Manufacturer: MuRata; Polarized: N; CompType: Capacitor; Value: 0.47uF; U/M: EA; Cap_F: 0.00000047; Tolerance_%: 10; Value1: Unknown; VDC_V: 16; Value2: 16V; TaMin_C: -55; TaMax_C: 125; Cap_Case: 0603; AEC Category: Q200
signal-integrity model Cap
simulation model Cap
footprint 0603
footprint 0603M
footprint 0603L
footprint 0603_HV
footprint 0603S
pins: 1, 2

## GRM188R71E105KA12D
designator C?  ValueDisplayed: 1µF  (hidden comment: GRM188R71E105KA12D)
CAP, CERM, 1 µF, 25 V, +/- 10%, X7R, 0603; Manufacturer: MuRata; Polarized: N; CompType: Capacitor; Value: 1uF; U/M: EA; Cap_F: 0.000001; Tolerance_%: 10; Value1: Unknown; VDC_V: 25; Value2: 25V; TaMin_C: -55; TaMax_C: 125; Cap_Case: 0603
signal-integrity model Cap
simulation model Cap
footprint 0603
footprint 0603M
footprint 0603L
footprint 0603_HV
footprint 0603S
pins: 1, 2

## GRM188R71E153KA01D
designator C?  ValueDisplayed: 0.015µF  (hidden comment: GRM188R71E153KA01D)
CAP, CERM, 0.015 µF, 25 V, +/- 10%, X7R, 0603; Manufacturer: MuRata; Polarized: N; CompType: Capacitor; Value: 0.015uF; U/M: EA; Cap_F: 0.000000015; Tolerance_%: 10; Value1: Unknown; VDC_V: 25; Value2: 25V; TaMin_C: -55; TaMax_C: 125; Cap_Case: 0603
signal-integrity model Cap
simulation model Cap
footprint 0603
footprint 0603M
footprint 0603L
footprint 0603_HV
footprint 0603S
pins: 1, 2

## GRM188R72A104KA35D
designator C?  ValueDisplayed: 0.1µF  (hidden comment: GRM188R72A104KA35D)
CAP, CERM, 0.1 µF, 100 V, +/- 10%, X7R, 0603; Manufacturer: MuRata; Polarized: N; CompType: Capacitor; Value: 0.1uF; U/M: EA; Cap_F: 0.0000001; Tolerance_%: 10; Value1: Unknown; VDC_V: 100; Value2: 100V; TaMin_C: -55; TaMax_C: 125; Cap_Case: 0603; AEC Category: Q200
signal-integrity model Cap
simulation model Cap
footprint 0603
footprint 0603M
footprint 0603L
footprint 0603_HV
footprint 0603S
pins: 1, 2

## Inductor_Iron
designator L?, comment ValueDisplayed: 3.3uH  (hidden comment: SER2915H-332KL)
Inductor, Shielded E Core, Ferrite, 3.3 uH, 30 A, 0.00186 ohm, SMD; Manufacturer: Coilcraft; Isat: 68.4A @ 30% inductance drop; Irms: 30A @ 40C rise; Green_Lifecycle: Not Set; SizeAreaWB_mm2: 651.82; DCR_ohm: 1.86m; Green_REACh: Incomplete; Value: 3.3uH; Imax_A: 30A; SizeZ_mm: 15.36; SizeX_mm: 27.9; SizeY_mm: 19.8; SizeArea_mm2: 552.42; Ind_H: 3.3µH; AEC Category: Q200
footprint SER2915H (COILCRAFT)
pins: 1, 2

## LM26LVCISD-145/NOPB
designator U?
1.6V Factory Preset Temperature Switch and Temperature Sensor, 6-pin LLP, Pb-Free; Manufacturer: Texas Instruments; PackageTopMarking: XTT*145; PowerWise: Y; CompType: Temp Sensor IC
footprint SDB06A (SON, 6-Leads, Body 2.2x2.5mm, Pitch 0.65mm, NSC Recommended (SC-70 Land))
pins: 1 TRIP TEST (in), 2 GND (power) "Ground", 3 ~{OVERTEMP} (oc), 4 VDD (power), 5 OVERTEMP (out), 6 VTEMP (out), 7 DAP (power) "Ground"

## LM4040AIM3X-2.0
designator U?
Precision Micropower Shunt Voltage Reference, 3-pin SOT-23; Manufacturer: Texas Instruments; PackageTopMarking: RJA*XTT; PowerWise: N; CompType: Voltage Reference IC
footprint MF03A_N (SOT23, 3-Leads, Body 2.9x1.3mm, Pitch 0.95mm, Lead Span 2.4mm, IPC Medium Density)
footprint MF03A_L (SOT23, 3-Leads, Body 2.9x1.3mm, Pitch 0.95mm, Lead Span 2.4mm, IPC High Density)
footprint MF03A_M (SOT23, 3-Leads, Body 2.9x1.3mm, Pitch 0.95mm, Lead Span 2.4mm, IPC Low Density)
pins: 1 +V, 2 -V, 3 NC

## LM5118MH/NOPB
designator U?
Wide Voltage Range Buck-Boost Controller, 20-pin TSSOP-EP, Pb-Free; Manufacturer: Texas Instruments; PackageTopMarking: NSUZXYTT*LM5118*MH; PowerWise: Y; CompType: Switcher
footprint MXA20A_N (TSOP, 20-Leads, Body 6.5x4.4mm, Pitch 0.65mm, Exposed Pad, IPC Medium Density)
footprint MXA20A_L (TSOP, 20-Leads, Body 6.5x4.4mm, Pitch 0.65mm, Exposed Pad, IPC High Density)
footprint MXA20A_M (TSOP, 20-Leads, Body 6.5x4.4mm, Pitch 0.65mm, Exposed Pad, IPC Low Density)
pins: 1 VIN (power), 2 UVLO (in), 3 RT (in), 4 EN (in), 5 RAMP (in), 6 AGND (power), 7 SS (in), 8 FB (in), 9 COMP (out), 10 VOUT (power), 11 SYNC (hiz), 12 CS (in), 13 CSG (in), 14 PGND (power), 15 LO (out), 16 VCC (power), 17 VCCX (power), 18 HB (in), 19 HO (out), 20 HS (in), 21 EP (power)

## LM5170_PreIC
designator U?, comment LM5170
IC, Controller, Bi-Directional; Manufacturer: Texas Instruments; SymbolCreator: a0413446; U/M: EA, IN, or GM
footprint PHP0048D_L (Thin QFP, 48-Leads, Body 7x7mm, Pitch 0.5mm, Thermal Pad 4.5x4.5mm, IPC High Density)
footprint PHP0048D_M (Thin QFP, 48-Leads, Body 7x7mm, Pitch 0.5mm, Thermal Pad 4.5x4.5mm, IPC Low Density)
footprint PHP0048D_N (Thin QFP, 48-Leads, Body 7x7mm, Pitch 0.5mm, Thermal Pad 4.5x4.5mm, IPC Medium Density)
signal-integrity model Model Name (Model Description)
pins: 1 CS2A, 2 CS2B, 4 VINX, 6 VIN, 8 RAMP2, 9 OVPA, 10 UVLO, 11 COMP2, 12 SS, 13 SW2, 14 HB2, 15 HO2, 17 LO2, 18 PGND, 19 VCC, 20 LO1, 22 HO1, 23 HB1, 24 SW1, 25 OVPB, 26 COMP1, 27 nFAULT, 28 RAMP1, 29 OPT, 30 IPK, 31 VCCA, 33 BRKS, 34 BRKG, 35 CS1B, 36 CS1A, 37 IOUT1, 38 IOUT2, 39 EN1, 40 SYNCIN, 41 SYNCOUT, 42 ISETD, 43 EN2, 44 DIR, 45 ISETA, 46 AGND, 47 OSC, 48 DT, 49 DAP

## LM6142AIM
designator U?
17MHz Rail-to-Rail Input and Output Op Amp, D0008A; Manufacturer: Texas Instruments; CompType: OpAmp IC
footprint D0008A_N
footprint D0008A_M
footprint D0008A_L
simulation model LM6142A/NS (SUBCKT)
pins on every part: 4 V- (power), 8 V+ (power)
part A pins: 1 OUT (out), 2 IN- (in), 3 IN+ (in)
part B pins: 5 IN+ (in), 6 IN- (in), 7 OUT (out)
1 alternate drawing of the same symbol

## MOSFET_N_D3G1S2
designator Q?, comment BSS123W-7-F
MOSFET, N-CH, 100 V, 0.17 A, SOT-323; Alternate Manufacturer: None; Manufacturer: Diodes Inc.; SizeZ_mm: 1.1; ChType: N; Value1: 1; VdsMax_V: 100V; SizeX_mm: 2.2; Vgs_V: 20V; Value: 100V; Rdson45_ohm: 10; SizeArea_mm2: 4.84; AEC Category: Q101; IdsMax_A: 1.7dA; SizeAreaWB_mm2: 10.24; U/M: EA
footprint SOT-323 (Diodes Inc recommended land pattern.  2016-02-24)
pins: 1 G, 2 S, 3 D

## Net-Tie
designator NT?  (net tie, no BOM)
Single point connection between nets.; SymbolCreator: codlsc
footprint Net-Tie_10mil (10mil net tie, no solder mask opening, no solder paste)
footprint NetTie_1206 (1206 pads tied by 10mil copper trace which can be cut.  Part can be placed on pads.)
footprint Net-Tie_0805_HV
footprint NetTie_1206_NoOverlay (1206 pads tied by 10mil copper trace which can be cut.  Part can be placed on pads.)
footprint Net-Tie_0805_HV_NoOverlay (0805_HV pads tied by 10mil copper trace which can be cut.  An 0805 part can be placed on pads.)
footprint Net-Tie_10milWide_30milLong
footprint Net-Tie_20milWide_60milLong
footprint NetTie_0603
footprint NetTie_0402
footprint Net-Tie_50milWide_30milLong
pins: 1, 2

## NVMFS5C628NLT1G
designator Q?
MOSFET N-CH 60V SO8FL; Manufacturer: Used in BOM report; SymbolVersion: use current date i.e. 2008-05-20; SymbolCreator: Use a-id; CompType: Used in some BOM reports.  Useful for finding later.; U/M: EA, IN, or GM; Rds On Max: 2.4mR; Input Capacitance: 3.6nF; Max Power Dissipation: 3.7W
footprint PG-TDSON-8 (Infineon recommended land pattern)
pins: 1 S, 2 S, 3 S, 4 G, 5 D, 6 D, 7 D, 8 D, 9 D

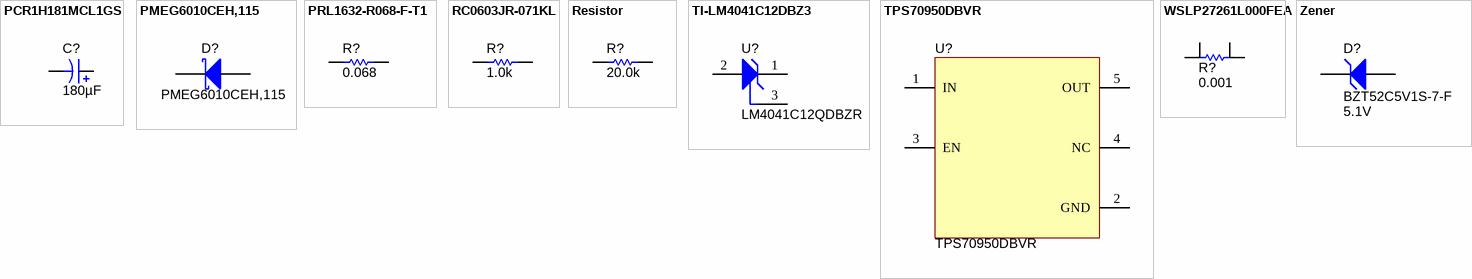
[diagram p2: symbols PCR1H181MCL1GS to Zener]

## PCR1H181MCL1GS
designator C?  ValueDisplayed: 180µF  (hidden comment: PCR1H181MCL1GS)
CAP, AL, 180 µF, 50 V, +/- 20%, 0.019 ohm, SMD; Manufacturer: Nichicon; Polarized: Y; CompType: Capacitor; Value: 180uF; U/M: EA; Cap_F: 0.00018; Tolerance_%: 20; VDC_V: 50; Value2: 50V; ESR_ohm: 0.019; IRMS_A: 3.5; TaMin_C: -55; TaMax_C: 125; Cap_Case: 10x12.7mm
signal-integrity model Cap
simulation model Cap
footprint CR_1000x1270
pins: 1 +, 2 -

## PMEG6010CEH,115
designator D?
Diode, Schottky, 60 V, 1 A, SOD-123F; Manufacturer: NXP Semiconductor; U/M: EA; Vf_V: 0.57; Value: 60V; Value1: 1A; Value2: 0.57V; Io_A: 1; Vr_V: 60; TJmax_C: 150
signal-integrity model Diode
footprint SOD-123F
pins: 1 K, 2 A

## PRL1632-R068-F-T1
designator R?  ValueDisplayed: 0.068  (hidden comment: PRL1632-R068-F-T1)
RES, 0.068, 1%, 1 W, 0612; Manufacturer: Susumu Co Ltd; CompType: Resistor; Value: 0.068; Value_Code: R068; Tolerance_%: 1; Value2: 1W; TempCo: 50 ppm/C; U/M: EA
signal-integrity model Resistor
simulation model Resistor
footprint 0612
pins: 1, 2

## RC0603JR-071KL
designator R?  ValueDisplayed: 1.0k  (hidden comment: RC0603JR-071KL)
RES, 1.0 k, 5%, 0.1 W, 0603; Manufacturer: Yageo America; CompType: Resistor; Value: 1.0k; Res_ohm: 1000; Value_Code: 1k00; Tolerance_%: 5; Power_W: 0.1; Value2: 0.1W; VDC_V: 50; TempCo: 100 ppm/C; EIA_Code: E24; U/M: EA
signal-integrity model Resistor
simulation model Resistor
footprint 0603
footprint 0603M
footprint 0603L
footprint 0603_HV
footprint 0603S
pins: 1, 2

## Resistor
designator R?, comment ValueDisplayed: 20.0k  (hidden comment: RT0603DRE0720KL)
RES, 20.0 k, 0.5%, 0.1 W, 0603; Manufacturer: Yageo America; Power_W: 100mW; TempCo: 50 ppm/C; Value_Code: 20k0; U/M: EA; Value: 20.0k; EIA_Code: E192; Res_ohm: 20k; SizeX_mm: 1.6; SizeY_mm: 0.8; SizeZ_mm: 1; Value2: 0.1W; SizeArea_mm2: 1.28; CompType: Resistor; VDC_V: 75V; AEC Category: Q200
footprint 0603 (0603 from SM-752 data)
footprint 0603_HV (Ernesto recommended land pattern.  26 mil between pads.)
footprint 0603L (0603 from SM-752 data)
footprint 0603S
footprint 0603M (0603 from SM-752 data)
pins: 1, 2

## TI-LM4041C12DBZ3
designator U?, comment LM4041C12QDBZR
1.2-V Precision Micropower Shunt Voltage Reference, 0.5% accuracy, 15 ppm / degC, 12 mA, -40 to 125 degC, 3-pin SOT-23 (DBZ), Green (RoHS & no Sb/Br); Manufacturer: Texas Instruments; Temp Coeff(Max)(ppm/ degree C): 100; Iout/Iz(Max)(mA): 12; Initial Accuracy @ 25/deg C(%): 0.5; Temp Coeff(Typ)(ppm/ degree C): 15; Rating: Catalog; VO(V): 1.225; Min Iz for Regulation(uA): 60
footprint DBZ0003A_N (SOT23, 3-Leads, Body 2.9x1.3mm, Pitch 0.95mm, Lead Span 2.4mm, IPC Medium Density)
footprint DBZ0003A_M (SOT23, 3-Leads, Body 2.9x1.3mm, Pitch 0.95mm, Lead Span 2.4mm, IPC Low Density)
footprint DBZ0003A_L (SOT23, 3-Leads, Body 2.9x1.3mm, Pitch 0.95mm, Lead Span 2.4mm, IPC High Density)
pins: 1 CATHODE, 2 ANODE, 3 NC

## TPS70950DBVR
designator U?
150-mA, 30-V, 1-uA IQ Voltage Regulators with Enable, DBV0005A; Alternate PartNumber: TPS70950DBVT; Manufacturer: Texas Instruments; SymbolCreator: Altium; CompType: IC; U/M: EA
footprint DBV0005A_N
footprint DBV0005A_M
footprint DBV0005A_L
pins: 1 IN (power) "Unregulated input to the device", 2 GND (power) "Ground", 3 EN (hiz) "Enable pin", 4 NC "No internal connection", 5 OUT (power) "Regulated output voltage."

## WSLP27261L000FEA
designator R?  ValueDisplayed: 0.001  (hidden comment: WSLP27261L000FEA)
Current Sense Resistors - SMD 0.001ohms 1%; Manufacturer: Vishay / Dale; SymbolVersion: use current date i.e. 2008-05-20; SymbolCreator: Use a-id; CompType: Used in some BOM reports.  Useful for finding later.; U/M: EA, IN, or GM; Case Width: 6.6 mm; Case Height: 3 mm; Case Length: 6.9 mm; TempCo: 75 PPM / C; Power_W: 7 W
footprint RES_WSL2726 (Vishay Dale)
pins: 1, 2, 3, 4

## Zener
designator D?, comment BZT52C5V1S-7-F  value 5.1V
Diode, Zener, 5.1 V, 200 mW, SOD-323; Manufacturer: Diodes Inc.; Power_W: 200mW; SizeAreaWB_mm2: 8.695; Value1: 0.2W; RJA_CperW: 625; U/M: EA; SizeZ_mm: 1; SizeX_mm: 2.7; SizeY_mm: 1.35; SizeArea_mm2: 3.645; AEC Category: Q101
footprint SOD-323 (NXP recommended land pattern)
pins: 1 K, 2 A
